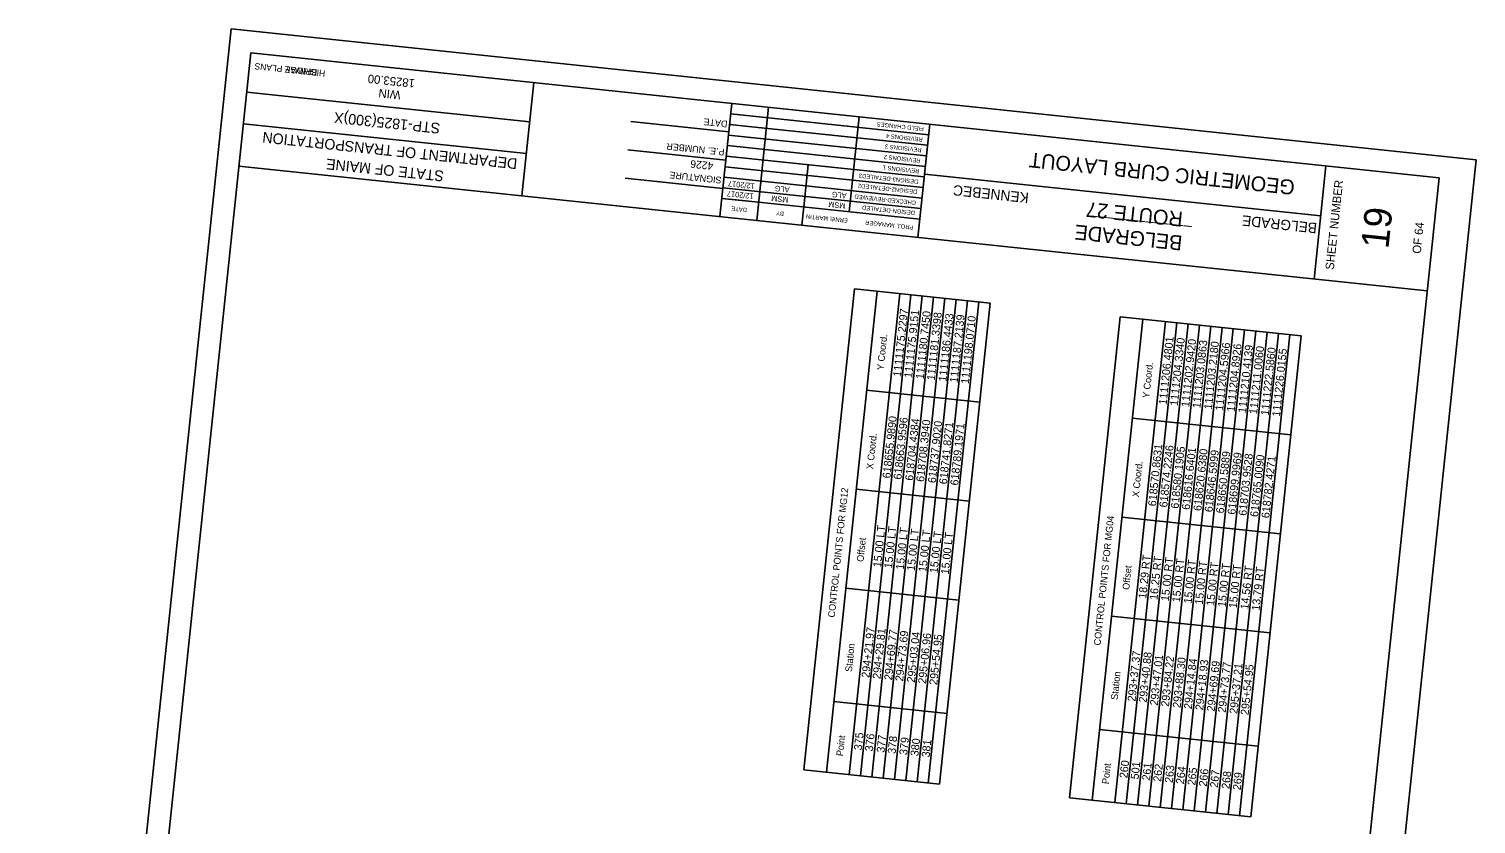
# Model space of a CAD drawing. Extents: x 1111051 to 1111686, y 618367 to 619270.
# Drawn here: x 1111051 to 1111686, y 618921 to 619270 of the extents above; entities that cross this region are included whole.
import ezdxf

# ---------------------------------------------------------------- set-up
doc = ezdxf.new("R2010")
doc.units = 0
for name, color, linetype in [('ANNOTATION', 7, 'Continuous'), ('BORDER', 7, 'Continuous'), ('BRIDGE_TITLE', 7, 'Continuous'), ('H_V CONTROLS', 7, 'Continuous'), ('HIGHWAY_TITLE', 7, 'Continuous'), ('PLOT BOUNDARY', 7, 'Continuous')]:
    doc.layers.add(name, color=color, linetype=linetype)

msp = doc.modelspace()

# ---------------------------------------------------------------- linework, layer by layer
at = {"layer": 'BORDER'}
for p, q in [((1111148.14, 619259.69), (1111064.52, 618464.07)), ((1111670.25, 619204.81), (1111148.13, 619259.69)), ((1111267.26, 619196.9), (1111272.48, 619246.62)), ((1111270.65, 619229.34), (1111146.34, 619242.4)), ((1111354.23, 619187.75), (1111359.46, 619237.48)), ((1111269.19, 619215.44), (1111144.88, 619228.5)), ((1111358.15, 619225.05), (1111315.15, 619229.57)), ((1111441.25, 619178.61), (1111446.48, 619228.33)), ((1111356.85, 619212.62), (1111313.85, 619217.14)), ((1111665.02, 619155.09), (1111142.9, 619209.96)), ((1111615.3, 619160.31), (1111620.52, 619210.04)), ((1111355.54, 619200.18), (1111312.54, 619204.7)), ((1111618.22, 619188.12), (1111444.18, 619206.41)), ((1111586.64, 618409.2), (1111670.26, 619204.81))]:
    msp.add_line(p, q, dxfattribs=at)
for points in [[(1111370.4, 619186.05), (1111375.62, 619235.78)], [(1111445.49, 619219.07), (1111358.49, 619228.22)], [(1111445.98, 619223.71), (1111358.97, 619232.85)], [(1111411.02, 619189.9), (1111415.4, 619231.6)], [(1111445.01, 619214.44), (1111358, 619223.58)], [(1111444.03, 619205.17), (1111357.03, 619214.32)], [(1111444.52, 619209.81), (1111357.51, 619218.95)], [(1111443.55, 619200.54), (1111356.54, 619209.69)], [(1111391.13, 619191.99), (1111393.08, 619210.53)], [(1111356.05, 619205.05), (1111443.06, 619195.91)], [(1111371.24, 619194.08), (1111355.08, 619195.78)], [(1111442.57, 619191.28), (1111355.57, 619200.42)], [(1111442.08, 619186.64), (1111358.59, 619195.42)], [(1111390.29, 619183.96), (1111391.13, 619192)]]:
    msp.add_lwpolyline(points, dxfattribs=at)
at = {"layer": 'H_V CONTROLS'}
for p, q in [((1111391.12, 618944.74), (1111413.33, 619156.07)), ((1111401.06, 618943.69), (1111423.27, 619155.03)), ((1111411.01, 618942.65), (1111433.22, 619153.98)), ((1111413.33, 619156.07), (1111473, 619149.8)), ((1111415.98, 618942.12), (1111438.19, 619153.46)), ((1111420.95, 618941.6), (1111443.16, 619152.94)), ((1111425.92, 618941.08), (1111448.14, 619152.42)), ((1111430.9, 618940.56), (1111453.11, 619151.89)), ((1111435.87, 618940.03), (1111458.08, 619151.37)), ((1111440.84, 618939.51), (1111463.05, 619150.85)), ((1111445.81, 618938.99), (1111468.03, 619150.32)), ((1111450.79, 618938.47), (1111473, 619149.8)), ((1111450.79, 618938.47), (1111473, 619149.8)), ((1111507.88, 618932.47), (1111530.09, 619143.8)), ((1111517.83, 618931.42), (1111540.04, 619142.76)), ((1111527.77, 618930.37), (1111549.98, 619141.71)), ((1111530.09, 619143.8), (1111609.65, 619135.44)), ((1111532.74, 618929.85), (1111554.96, 619141.19)), ((1111537.72, 618929.33), (1111559.93, 619140.67)), ((1111542.69, 618928.81), (1111564.9, 619140.14)), ((1111547.66, 618928.28), (1111569.87, 619139.62)), ((1111552.63, 618927.76), (1111574.85, 619139.1)), ((1111557.61, 618927.24), (1111579.82, 619138.57)), ((1111562.58, 618926.72), (1111584.79, 619138.05)), ((1111567.55, 618926.19), (1111589.76, 619137.53)), ((1111572.52, 618925.67), (1111594.74, 619137.01)), ((1111577.5, 618925.15), (1111599.71, 619136.48)), ((1111582.47, 618924.63), (1111604.68, 619135.96)), ((1111587.44, 618924.1), (1111609.65, 619135.44)), ((1111587.44, 618924.1), (1111609.65, 619135.44)), ((1111418.7, 619111.52), (1111468.43, 619106.29)), ((1111535.47, 619099.25), (1111605.08, 619091.93)), ((1111414.13, 619068.01), (1111463.85, 619062.78)), ((1111530.89, 619055.74), (1111600.51, 619048.42)), ((1111409.55, 619024.5), (1111459.28, 619019.27)), ((1111526.32, 619012.23), (1111595.94, 619004.91)), ((1111404.33, 618974.77), (1111454.05, 618969.55)), ((1111521.09, 618962.5), (1111590.71, 618955.18)), ((1111391.12, 618944.74), (1111450.79, 618938.47)), ((1111507.88, 618932.47), (1111587.44, 618924.1))]:
    msp.add_line(p, q, dxfattribs=at)
at = {"layer": 'PLOT BOUNDARY'}
msp.add_lwpolyline([(1111597.62, 618367.35), (1111686.47, 619212.69), (1111139.49, 619270.18), (1111050.64, 618424.84)], close=True, dxfattribs=at)

# ---------------------------------------------------------------- texts
at = {"layer": 'ANNOTATION'}
for s, height, rotation, p in [('4226', 3.396, 174, (1111351.46, 619211.57)), ('1111175.2297', 3.5156, 84, (1111433.8, 619117.26)), ('1111175.9151', 3.5156, 84, (1111438.66, 619116.75)), ('1111180.7450', 3.5156, 84, (1111443.76, 619116.21)), ('1111181.3398', 3.5156, 84, (1111448.62, 619115.7)), ('1111186.4433', 3.5156, 84, (1111453.75, 619115.16)), ('1111187.2139', 3.5156, 84, (1111458.66, 619114.65)), ('1111198.0710', 3.5156, 84, (1111463.58, 619114.13)), ('1111206.4801', 3.5156, 84, (1111550.5, 619104.99)), ('1111204.3340', 3.5156, 84, (1111555.42, 619104.48)), ('1111202.9420', 3.5156, 84, (1111560.42, 619103.95)), ('1111203.0863', 3.5156, 84, (1111565.3, 619103.44)), ('1111203.2180', 3.5156, 84, (1111570.4, 619102.9)), ('1111204.5966', 3.5156, 84, (1111575.33, 619102.38)), ('1111204.8926', 3.5156, 84, (1111580.35, 619101.86)), ('1111210.4139', 3.5156, 84, (1111585.38, 619101.33)), ('1111211.0060', 3.5156, 84, (1111590.24, 619100.82)), ('1111222.5860', 3.5156, 84, (1111595.35, 619100.28)), ('1111226.0155', 3.5156, 84, (1111600.29, 619099.76)), ('618655.9890', 3.5156, 84, (1111429.12, 619072.67)), ('618663.9596', 3.5156, 84, (1111433.97, 619072.16)), ('618704.4384', 3.5156, 84, (1111439.08, 619071.63)), ('618708.3940', 3.5156, 84, (1111443.93, 619071.12)), ('618737.9020', 3.5156, 84, (1111449.06, 619070.58)), ('618741.8271', 3.5156, 84, (1111453.97, 619070.06)), ('618789.1971', 3.5156, 84, (1111458.9, 619069.54)), ('618570.8631', 3.5156, 84, (1111545.81, 619060.41)), ('618574.2246', 3.5156, 84, (1111550.74, 619059.89)), ('618580.1905', 3.5156, 84, (1111555.74, 619059.36)), ('618616.6401', 3.5156, 84, (1111560.61, 619058.85)), ('618620.6380', 3.5156, 84, (1111565.72, 619058.32)), ('618646.5999', 3.5156, 84, (1111570.64, 619057.8)), ('618650.5889', 3.5156, 84, (1111575.66, 619057.27)), ('618699.9969', 3.5156, 84, (1111580.7, 619056.74)), ('618703.9528', 3.5156, 84, (1111585.55, 619056.23)), ('618765.0090', 3.5156, 84, (1111590.66, 619055.69)), ('618782.4271', 3.5156, 84, (1111595.61, 619055.17)), ('15.00 LT', 3.516, 84, (1111425.01, 619033.61)), ('15.00 LT', 3.516, 84, (1111429.87, 619033.1)), ('15.00 LT', 3.516, 84, (1111434.97, 619032.56)), ('15.00 LT', 3.516, 84, (1111439.83, 619032.05)), ('15.00 LT', 3.516, 84, (1111444.95, 619031.51)), ('15.00 LT', 3.516, 84, (1111449.86, 619031)), ('15.00 LT', 3.516, 84, (1111454.79, 619030.48)), ('18.29 RT', 3.516, 84, (1111541.54, 619019.78)), ('16.25 RT', 3.516, 84, (1111546.47, 619019.26)), ('15.00 RT', 3.516, 84, (1111551.47, 619018.73)), ('15.00 RT', 3.516, 84, (1111556.34, 619018.22)), ('15.00 RT', 3.516, 84, (1111561.45, 619017.68)), ('15.00 RT', 3.516, 84, (1111566.37, 619017.17)), ('15.00 RT', 3.516, 84, (1111571.39, 619016.64)), ('15.00 RT', 3.516, 84, (1111576.43, 619016.11)), ('15.00 RT', 3.516, 84, (1111581.28, 619015.6)), ('14.56 RT', 3.516, 84, (1111586.39, 619015.06)), ('13.79 RT', 3.516, 84, (1111591.33, 619014.54)), ('294+21.97', 3.516, 84, (1111419.91, 618985.05)), ('294+29.81', 3.516, 84, (1111424.76, 618984.54)), ('294+69.77', 3.516, 84, (1111429.87, 618984.01)), ('294+73.69', 3.516, 84, (1111434.72, 618983.5)), ('295+03.04', 3.516, 84, (1111439.85, 618982.96)), ('295+06.96', 3.516, 84, (1111444.76, 618982.44)), ('295+54.95', 3.516, 84, (1111449.69, 618981.92)), ('293+37.37', 3.516, 84, (1111536.79, 618974.63)), ('293+40.88', 3.516, 84, (1111541.72, 618974.12)), ('293+47.01', 3.516, 84, (1111546.64, 618972.87)), ('293+84.22', 3.516, 84, (1111551.52, 618972.36)), ('293+88.30', 3.516, 84, (1111556.63, 618971.82)), ('294+14.84', 3.516, 84, (1111561.55, 618971.3)), ('294+18.93', 3.516, 84, (1111566.57, 618970.78)), ('294+69.69', 3.516, 84, (1111571.61, 618970.25)), ('294+73.77', 3.516, 84, (1111576.46, 618969.74)), ('295+37.21', 3.516, 84, (1111581.57, 618969.2)), ('295+54.95', 3.516, 84, (1111586.51, 618968.68)), ('375', 3.516, 84, (1111416.56, 618953.23)), ('376', 3.516, 84, (1111421.42, 618952.72)), ('377', 3.516, 84, (1111426.52, 618952.18)), ('378', 3.516, 84, (1111431.38, 618951.67)), ('379', 3.516, 84, (1111436.51, 618951.14)), ('380', 3.516, 84, (1111441.42, 618950.62)), ('381', 3.516, 84, (1111446.34, 618950.1)), ('260', 3.516, 84, (1111533.26, 618940.97)), ('501', 3.516, 84, (1111538.18, 618940.45)), ('261', 3.516, 84, (1111543.18, 618939.92)), ('262', 3.516, 84, (1111548.06, 618939.41)), ('263', 3.516, 84, (1111553.16, 618938.87)), ('264', 3.516, 84, (1111558.09, 618938.36)), ('265', 3.516, 84, (1111563.11, 618937.83)), ('266', 3.516, 84, (1111568.14, 618937.3)), ('267', 3.516, 84, (1111573, 618936.79)), ('268', 3.516, 84, (1111578.11, 618936.25)), ('269', 3.516, 84, (1111583.05, 618935.73))]:
    msp.add_text(s, height=height, rotation=rotation, dxfattribs=at).set_placement(p)
at = {"layer": 'BORDER'}
for s, height, rotation, p in [('18253.00', 3.726, 174, (1111220.39, 619248.05)), ('WIN', 3.726, 174, (1111214.1, 619242.89)), ('STP-1825(300)X', 4.6588, 174, (1111231.51, 619228.77)), ('DATE', 2.953, 174, (1111357.69, 619229.83)), ('FIELD CHANGES', 1.8637, 174, (1111443.9, 619227.11)), ('DEPARTMENT OF TRANSPORTATION', 4.6588, 174, (1111265.39, 619213.21)), ('REVISIONS 4', 1.8637, 174, (1111443.41, 619222.48)), ('P.E. NUMBER', 2.9528, 174, (1111356.39, 619217.49)), ('REVISIONS 2', 1.8637, 174, (1111442.44, 619213.21)), ('REVISIONS 3', 1.8637, 174, (1111442.93, 619217.84)), ('GEOMETRIC CURB LAYOUT', 6.5214, 174, (1111607.11, 619203.73)), ('STATE OF MAINE', 4.6588, 174, (1111233.12, 619207.8)), ('REVISIONS 1', 1.8637, 174, (1111441.95, 619208.58)), ('SIGNATURE', 2.953, 174, (1111355.1, 619205.16)), ('12/2017', 2.423, 174, (1111369.6, 619202.31)), ('DESIGN2-DETAILED2', 1.8637, 174, (1111441, 619199.5)), ('DESIGN3-DETAILED3', 1.8637, 174, (1111441.46, 619203.95)), ('SHEET NUMBER', 3.7264, 84, (1111623.94, 619164.26)), ('12/2017', 2.423, 174, (1111369.13, 619197.87)), ('MSM', 2.423, 174, (1111384.46, 619196.25)), ('ALG', 2.423, 174, (1111384.93, 619200.7)), ('ALG', 2.423, 174, (1111410, 619198.07)), ('CHECKED-REVIEWED', 1.8637, 174, (1111440.49, 619194.68)), ('DATE', 1.857, 174, (1111366.17, 619191.55)), ('BY', 1.857, 174, (1111382.43, 619189.84)), ('MSM', 2.423, 174, (1111409.53, 619193.62)), ('DESIGN-DETAILED', 1.8637, 174, (1111440.02, 619190.23)), ('19', 12.097, 84, (1111647.94, 619173.33)), ('ERNIE MARTIN', 1.8637, 174, (1111410.5, 619186.89)), ('PROJ. MANAGER', 1.8637, 174, (1111439.35, 619183.86)), ('OF 64', 3.726, 84, (1111662.15, 619171.31))]:
    msp.add_text(s, height=height, rotation=rotation, dxfattribs=at).set_placement(p)
at = {"layer": 'BRIDGE_TITLE'}
for s, height, p in [('BRIDGE PLANS', 2.795, (1111177.42, 619252.38)), ('KENNEBEC', 4.536, (1111490.14, 619198.2)), ('_____________', 4.5358, (1111561.35, 619182.29)), ('BELGRADE', 4.536, (1111616.77, 619184.9))]:
    msp.add_text(s, height=height, rotation=174, dxfattribs=at).set_placement(p)
at = {"layer": 'H_V CONTROLS'}
for s, p in [('Y Coord.', (1111426.15, 619120.2)), ('Y Coord.', (1111542.91, 619107.93)), ('X Coord.', (1111421.57, 619076.69)), ('X Coord.', (1111538.34, 619064.42)), ('CONTROL POINTS FOR MG12', (1111404.67, 619011.55)), ('CONTROL POINTS FOR MG04', (1111521.44, 618999.27)), ('Offset', (1111417.3, 619035.98)), ('Offset', (1111534.06, 619023.71)), ('Station', (1111412.22, 618987.66)), ('Station', (1111528.98, 618975.38)), ('Point', (1111408.33, 618950.65)), ('Point', (1111525.09, 618938.38))]:
    msp.add_text(s, height=3, rotation=84, dxfattribs=at).set_placement(p)
at = {"layer": 'HIGHWAY_TITLE'}
for s, height, p in [('HIGHWAY PLANS', 2.795, (1111180.94, 619252.01)), ('ROUTE 27', 6.521, (1111557.91, 619189.77)), ('BELGRADE', 6.521, (1111557.69, 619179.3))]:
    msp.add_text(s, height=height, rotation=174, dxfattribs=at).set_placement(p)

doc.saveas('drawing.dxf')
